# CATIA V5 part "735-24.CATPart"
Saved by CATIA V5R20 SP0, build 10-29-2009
Part number: 735-24
Bounding box of the stored display mesh (mm): x -24 to 24, y -23.94 to 23.94, z -23 to 36
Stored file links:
  C:\Users\Utente\Desktop\IO LAVORO\3D X SITO CF\X SITO\735\735-24.CATPart
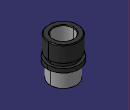
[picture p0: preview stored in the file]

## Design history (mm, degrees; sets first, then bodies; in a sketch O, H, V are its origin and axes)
Set1
  DatumSurface1 to DatumSurface25 "735-24"
Body1 (main body)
